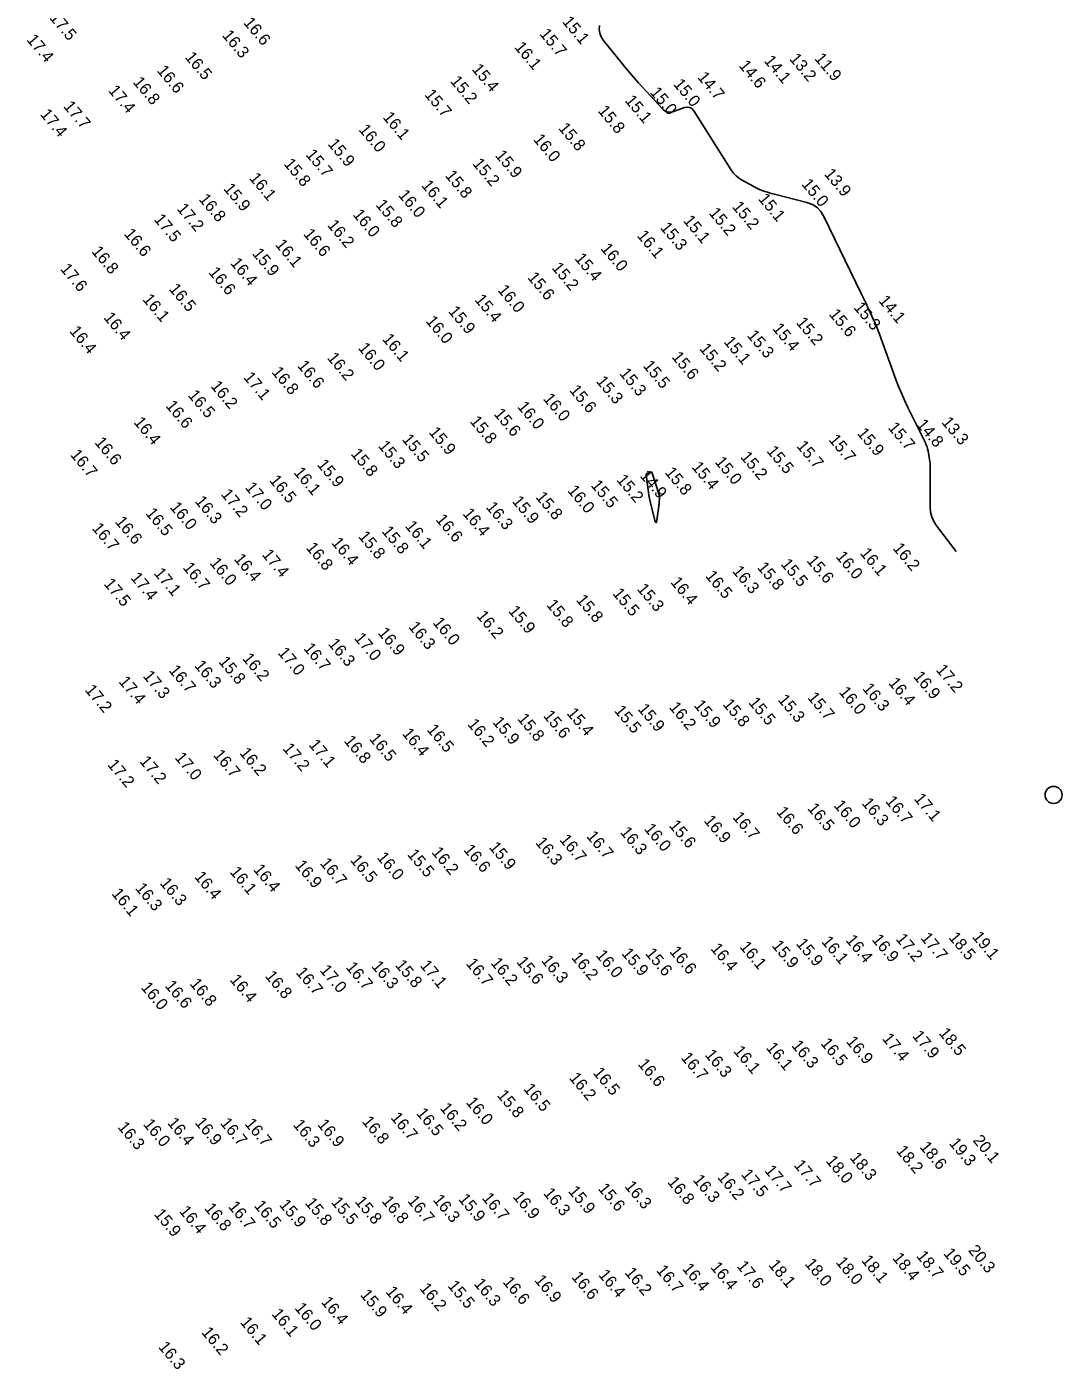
# Model space of a CAD drawing. Extents: x 988130 to 1132882, y 654656 to 841453.
# Drawn here: x 1110747 to 1111185, y 678117 to 678686 of the extents above; entities that cross this region are included whole.
import ezdxf

# ---------------------------------------------------------------- set-up
doc = ezdxf.new("R2010")
doc.units = 0
for name, color, linetype in [('V-CHAN-NAID', 7, 'Continuous'), ('V-TOPO-MAJR', 7, 'Continuous'), ('V-TOPO-SOUN', 7, 'Continuous')]:
    doc.layers.add(name, color=color, linetype=linetype)

msp = doc.modelspace()

# ---------------------------------------------------------------- linework, layer by layer
at = {"layer": 'V-CHAN-NAID'}
msp.add_circle((1111181.63, 678360.27), 3.6, dxfattribs=at)
at = {"layer": 'V-TOPO-MAJR'}
msp.add_lwpolyline([(1110989.43, 678686.06), (1110989.32, 678684.39), (1110989.54, 678682.81), (1110990.11, 678681.31), (1110991.02, 678679.91), (1110998.81, 678670.11), (1111000.48, 678668.04), (1111002.19, 678666), (1111003.95, 678664), (1111005.73, 678662.02), (1111016.24, 678650.64), (1111017.18, 678649.85), (1111018.19, 678649.41), (1111019.3, 678649.32), (1111020.49, 678649.58), (1111025.43, 678651.33), (1111026.6, 678651.57), (1111027.63, 678651.43), (1111028.53, 678650.9), (1111029.3, 678649.99), (1111045.32, 678624.74), (1111046.18, 678623.55), (1111047.18, 678622.49), (1111048.29, 678621.57), (1111049.54, 678620.79), (1111056.3, 678617.11), (1111056.86, 678616.82), (1111057.43, 678616.56), (1111058.01, 678616.32), (1111058.6, 678616.11), (1111061, 678615.31), (1111061.6, 678615.12), (1111062.2, 678614.94), (1111062.81, 678614.77), (1111063.42, 678614.61), (1111077.18, 678611.12), (1111079.5, 678610.28), (1111081.48, 678609.02), (1111083.12, 678607.33), (1111084.41, 678605.22), (1111100.19, 678572.58), (1111100.87, 678571.16), (1111101.55, 678569.74), (1111102.22, 678568.32), (1111102.89, 678566.9), (1111105.54, 678561.2), (1111106.19, 678559.77), (1111106.81, 678558.32), (1111107.39, 678556.86), (1111107.94, 678555.39), (1111114.88, 678536.18), (1111115.99, 678533.24), (1111117.18, 678530.34), (1111118.45, 678527.48), (1111119.8, 678524.64), (1111127.36, 678509.4), (1111127.73, 678508.57), (1111128.05, 678507.72), (1111128.3, 678506.85), (1111128.48, 678505.96), (1111129.11, 678502.37), (1111129.25, 678501.46), (1111129.34, 678500.56), (1111129.4, 678499.65), (1111129.42, 678498.74), (1111129.36, 678482.29), (1111129.53, 678480.08), (1111130.04, 678477.98), (1111130.91, 678476), (1111132.12, 678474.14), (1111140.41, 678463.33)], dxfattribs=at)
msp.add_lwpolyline([(1111009.28, 678496.27), (1111009.19, 678496.03), (1111009.19, 678495.74), (1111010.11, 678488.45), (1111010.3, 678487.13), (1111010.53, 678485.82), (1111010.8, 678484.51), (1111011.12, 678483.22), (1111012.86, 678476.59), (1111013.13, 678475.77), (1111013.36, 678475.51), (1111013.56, 678475.8), (1111013.73, 678476.64), (1111014.5, 678482.59), (1111014.55, 678482.98), (1111014.6, 678483.37), (1111014.64, 678483.77), (1111014.68, 678484.16), (1111014.84, 678485.74), (1111014.85, 678486.14), (1111014.83, 678486.53), (1111014.77, 678486.91), (1111014.68, 678487.29), (1111011.76, 678496.59), (1111011.64, 678496.85), (1111011.46, 678497), (1111011.24, 678497.05), (1111010.96, 678497), (1111009.73, 678496.59), (1111009.46, 678496.46)], close=True, dxfattribs=at)

# ---------------------------------------------------------------- texts
at = {"layer": 'V-TOPO-SOUN'}
for s, p in [('17.5 ', (1110756.35, 678689.25)), ('16.6 ', (1110838.44, 678687.15)), ('15.1 ', (1110973.38, 678687.59)), ('17.4 ', (1110746.68, 678679.96)), ('16.3 ', (1110829.41, 678681.8)), ('15.7 ', (1110963.78, 678682.4)), ('16.1 ', (1110953.15, 678676.81)), ('16.5 ', (1110813.67, 678672.55)), ('14.6 ', (1111048.12, 678669)), ('14.1 ', (1111058.77, 678671.03)), ('13.2 ', (1111069.5, 678671.87)), ('11.9 ', (1111080.15, 678672.01)), ('16.8 ', (1110791.64, 678661.99)), ('16.6 ', (1110801.81, 678666.87)), ('15.2 ', (1110925.97, 678662.39)), ('15.4 ', (1110935.12, 678667.48)), ('14.7 ', (1111030.6, 678664.07)), ('17.4 ', (1110781.26, 678658.42)), ('15.7 ', (1110915.08, 678656.68)), ('15.0 ', (1111010.52, 678657.65)), ('15.0 ', (1111020.4, 678661.14)), ('17.7 ', (1110762.23, 678651.72)), ('15.1 ', (1110999.9, 678654.21)), ('17.4 ', (1110752.39, 678648.36)), ('16.1 ', (1110897.41, 678647.14)), ('15.8 ', (1110988.47, 678649.82)), ('16.0 ', (1110887.24, 678641.88)), ('15.8 ', (1110971.78, 678642.49)), ('15.9 ', (1110874.14, 678635.79)), ('16.0 ', (1110961.11, 678637.76)), ('15.7 ', (1110864.77, 678631.31)), ('15.9 ', (1110944.97, 678630.96)), ('15.8 ', (1110855.5, 678627.38)), ('15.8 ', (1110923.8, 678622.41)), ('15.2 ', (1110935.41, 678627.47)), ('13.9 ', (1111084.22, 678623.12)), ('15.9 ', (1110829.97, 678616.88)), ('16.1 ', (1110840.86, 678621.36)), ('16.1 ', (1110913.77, 678618.26)), ('15.0 ', (1111074.67, 678618.8)), ('16.8 ', (1110819.53, 678612.42)), ('16.0 ', (1110903.94, 678614.16)), ('15.1 ', (1111056.34, 678612.57)), ('17.2 ', (1110810.26, 678608.37)), ('16.0 ', (1110884.73, 678605.92)), ('15.8 ', (1110894.42, 678610.02)), ('15.2 ', (1111035.43, 678606.58)), ('15.2 ', (1111045.3, 678609.22)), ('17.5 ', (1110800.54, 678603.88)), ('16.2 ', (1110873.93, 678601.45)), ('15.3 ', (1111014.82, 678600.37)), ('15.1 ', (1111024.58, 678603.33)), ('16.6 ', (1110787.88, 678597.71)), ('16.6 ', (1110863.78, 678597.69)), ('16.1 ', (1111005.02, 678596.98)), ('16.8 ', (1110774.14, 678590.31)), ('15.9 ', (1110842.15, 678589.41)), ('16.1 ', (1110851.87, 678593.17)), ('16.0 ', (1110989.68, 678591.47)), ('17.6 ', (1110760.9, 678582.89)), ('16.4 ', (1110832.9, 678585.36)), ('15.2 ', (1110968.94, 678583.37)), ('15.4 ', (1110978.64, 678587.31)), ('16.6 ', (1110823.68, 678581.46)), ('15.6 ', (1110958.67, 678579.28)), ('16.5 ', (1110806.91, 678574.41)), ('16.0 ', (1110946.02, 678573.94)), ('16.1 ', (1110795.73, 678570.02)), ('15.4 ', (1110936.3, 678569.86)), ('15.3 ', (1111096.74, 678566.57)), ('14.1 ', (1111107.27, 678569.44)), ('16.4 ', (1110779.24, 678562.3)), ('16.0 ', (1110915.6, 678560.8)), ('15.9 ', (1110925.14, 678564.94)), ('15.2 ', (1111072.36, 678560.16)), ('15.6 ', (1111086.29, 678563.7)), ('16.4 ', (1110764.81, 678556.53)), ('15.3 ', (1111051.59, 678554.73)), ('15.4 ', (1111062.34, 678557.65)), ('16.0 ', (1110886.98, 678549.41)), ('16.1 ', (1110897.19, 678553.21)), ('15.2 ', (1111031.45, 678549.11)), ('15.1 ', (1111041.73, 678552.05)), ('16.2 ', (1110873.87, 678545.24)), ('15.6 ', (1111019.72, 678545.61)), ('17.1 ', (1110838.44, 678536.98)), ('16.8 ', (1110850.39, 678539.23)), ('16.6 ', (1110861.24, 678541.91)), ('15.3 ', (1110997.56, 678538.64)), ('15.5 ', (1111007.55, 678541.87)), ('16.2 ', (1110824.55, 678533.28)), ('15.6 ', (1110976.41, 678531.52)), ('15.3 ', (1110987.72, 678535.32)), ('16.5 ', (1110814.93, 678529.39)), ('16.0 ', (1110965.28, 678527.93)), ('16.6 ', (1110805.49, 678524.95)), ('15.6 ', (1110944.38, 678521.52)), ('16.0 ', (1110954.37, 678524.54)), ('16.4 ', (1110791.99, 678517.97)), ('15.8 ', (1110934.28, 678518.37)), ('15.7 ', (1111111.26, 678515.7)), ('14.8 ', (1111123.36, 678516.99)), ('13.3 ', (1111133.96, 678517.96)), ('16.6 ', (1110775.42, 678509.44)), ('15.5 ', (1110905.57, 678510.71)), ('15.9 ', (1110916.89, 678513.75)), ('15.7 ', (1111086.17, 678510.57)), ('15.9 ', (1111098.18, 678513.29)), ('16.7 ', (1110765.14, 678504.21)), ('15.8 ', (1110883.89, 678504.59)), ('15.3 ', (1110895.47, 678507.93)), ('15.2 ', (1111048.8, 678503.26)), ('15.5 ', (1111059.92, 678505.76)), ('15.7 ', (1111072.54, 678507.91)), ('15.9 ', (1110869.59, 678500.02)), ('15.4 ', (1111028.18, 678499.02)), ('15.0 ', (1111037.97, 678501.15)), ('16.5 ', (1110849.4, 678493.35)), ('16.1 ', (1110859.7, 678496.7)), ('15.2 ', (1110996.35, 678493.58)), ('14.9 ', (1111006.24, 678495.32)), ('15.8 ', (1111016.79, 678496.7)), ('17.2 ', (1110828.95, 678487.45)), ('17.0 ', (1110839.11, 678490.33)), ('15.8 ', (1110962.09, 678486.27)), ('16.0 ', (1110975.61, 678489.04)), ('15.5 ', (1110985.49, 678491.26)), ('16.0 ', (1110807.3, 678482)), ('16.3 ', (1110817.88, 678484.52)), ('16.3 ', (1110941.06, 678482.03)), ('15.9 ', (1110952.13, 678484.53)), ('16.6 ', (1110784.11, 678475.85)), ('16.5 ', (1110797, 678479.43)), ('16.6 ', (1110919.81, 678476.77)), ('16.4 ', (1110931.24, 678479.29)), ('16.7 ', (1110774.32, 678473.1)), ('15.8 ', (1110887.05, 678469.62)), ('15.8 ', (1110896.98, 678471.78)), ('16.1 ', (1110906.87, 678474)), ('16.8 ', (1110864.91, 678464.84)), ('16.4 ', (1110875.69, 678466.94)), ('16.2 ', (1111113.3, 678464.61)), ('16.0 ', (1110824.14, 678458.4)), ('16.4 ', (1110834.46, 678460.06)), ('17.4 ', (1110846.28, 678461.93)), ('15.5 ', (1111065.88, 678457.93)), ('15.6 ', (1111076.87, 678459.34)), ('16.0 ', (1111089.15, 678461.07)), ('16.1 ', (1111099.42, 678462.54)), ('17.4 ', (1110790.64, 678452.13)), ('17.1 ', (1110800.53, 678454.05)), ('16.7 ', (1110812.78, 678456.41)), ('16.5 ', (1111033.96, 678452.89)), ('16.3 ', (1111045.34, 678454.95)), ('15.8 ', (1111055.89, 678456.49)), ('17.5 ', (1110779.32, 678449.56)), ('15.3 ', (1111005.02, 678447.39)), ('16.4 ', (1111019.23, 678450.23)), ('15.8 ', (1110966.67, 678440.66)), ('15.8 ', (1110979.26, 678442.74)), ('15.5 ', (1110994.67, 678445.46)), ('16.2 ', (1110937.09, 678435.94)), ('15.9 ', (1110950.57, 678438.06)), ('16.3 ', (1110908.29, 678431.33)), ('16.0 ', (1110918.6, 678433.13)), ('16.3 ', (1110874.27, 678424.16)), ('17.0 ', (1110885.32, 678426.55)), ('16.9 ', (1110895.36, 678428.76)), ('16.2 ', (1110837.96, 678417.94)), ('17.0 ', (1110852.99, 678420.36)), ('16.7 ', (1110863.84, 678422.25)), ('16.7 ', (1110806.83, 678412.92)), ('16.3 ', (1110817.66, 678414.92)), ('15.8 ', (1110827.89, 678416.58)), ('17.2 ', (1111131.56, 678413.15)), ('17.4 ', (1110785.62, 678408.17)), ('17.3 ', (1110795.89, 678410.52)), ('16.4 ', (1111111.45, 678407.59)), ('16.9 ', (1111121.98, 678410.26)), ('17.2 ', (1110771.36, 678404.59)), ('15.3 ', (1111064.65, 678400.45)), ('15.7 ', (1111077.16, 678401.42)), ('16.0 ', (1111090.49, 678403.74)), ('16.3 ', (1111100.46, 678405.21)), ('15.4 ', (1110975.27, 678394.73)), ('15.5 ', (1110995.37, 678395.84)), ('15.9 ', (1111005.36, 678396.54)), ('16.2 ', (1111018.6, 678397.28)), ('15.9 ', (1111029.08, 678398.12)), ('15.8 ', (1111041.31, 678398.57)), ('15.5 ', (1111052.24, 678399.27)), ('16.2 ', (1110933.27, 678390.13)), ('15.9 ', (1110943.87, 678391.02)), ('15.8 ', (1110954.4, 678392.41)), ('15.6 ', (1110965.32, 678393.7)), ('16.5 ', (1110891.66, 678383.96)), ('16.4 ', (1110905.57, 678386.15)), ('16.5 ', (1110916.06, 678387.8)), ('16.2 ', (1110836.76, 678377.94)), ('17.2 ', (1110855.04, 678379.83)), ('17.1 ', (1110866.08, 678381.42)), ('16.8 ', (1110880.99, 678383.06)), ('17.2 ', (1110780.87, 678372.96)), ('17.2 ', (1110794.43, 678374.42)), ('17.0 ', (1110809.37, 678375.95)), ('16.7 ', (1110825.65, 678377.07)), ('16.0 ', (1111088.32, 678355.71)), ('16.3 ', (1111100.15, 678356.67)), ('16.7 ', (1111110.16, 678357.5)), ('17.1 ', (1111122.26, 678358.56)), ('16.9 ', (1111033.34, 678349.28)), ('16.7 ', (1111045.47, 678350.76)), ('16.6 ', (1111064.02, 678352.95)), ('16.5 ', (1111077.17, 678354.46)), ('16.3 ', (1110997.87, 678344.4)), ('16.0 ', (1111008.04, 678345.8)), ('15.6 ', (1111018.55, 678347.24)), ('15.9 ', (1110942.37, 678338.02)), ('16.3 ', (1110962.01, 678340)), ('16.7 ', (1110972.23, 678341.18)), ('16.7 ', (1110983.6, 678342.65)), ('16.5 ', (1110883.64, 678332.57)), ('16.0 ', (1110894.91, 678333.69)), ('15.5 ', (1110907.79, 678334.95)), ('16.2 ', (1110918.09, 678335.89)), ('16.6 ', (1110931.58, 678336.94)), ('16.1 ', (1110832.64, 678327.57)), ('16.4 ', (1110842.59, 678328.61)), ('16.9 ', (1110860.25, 678330.29)), ('16.7 ', (1110870.82, 678331.24)), ('16.3 ', (1110803.06, 678322.83)), ('16.4 ', (1110817.64, 678325.51)), ('16.1 ', (1110782.65, 678318.37)), ('16.3 ', (1110792.63, 678320.66)), ('16.1 ', (1111083.08, 678298.1)), ('16.4 ', (1111093.36, 678298.68)), ('16.9 ', (1111104.44, 678298.91)), ('17.2 ', (1111114.55, 678299.18)), ('17.7 ', (1111125.06, 678299.6)), ('18.5 ', (1111136.93, 678299.78)), ('19.1 ', (1111146.93, 678300.06)), ('15.9 ', (1110998.49, 678293.05)), ('15.6 ', (1111008.5, 678293.04)), ('16.6 ', (1111018.79, 678293.85)), ('16.4 ', (1111036.19, 678295.1)), ('16.1 ', (1111048.45, 678295.89)), ('15.9 ', (1111062.08, 678296.36)), ('15.9 ', (1111072.35, 678297.18)), ('16.7 ', (1110881.75, 678287.19)), ('16.3 ', (1110892.65, 678287.63)), ('15.8 ', (1110902.66, 678288.1)), ('17.1 ', (1110913.17, 678287.95)), ('16.7 ', (1110932.63, 678288.77)), ('16.2 ', (1110943.11, 678289.01)), ('15.6 ', (1110954.03, 678289.49)), ('16.3 ', (1110964.49, 678290.05)), ('16.2 ', (1110977.22, 678291.34)), ('16.0 ', (1110987.55, 678292.28)), ('16.4 ', (1110832.66, 678281.89)), ('16.8 ', (1110847.58, 678283.45)), ('16.7 ', (1110860.64, 678284.98)), ('17.0 ', (1110870.73, 678285.96)), ('16.0 ', (1110795.04, 678278.66)), ('16.6 ', (1110805.18, 678279.36)), ('16.8 ', (1110815.71, 678280.22)), ('18.5 ', (1111132.76, 678259.31)), ('16.1 ', (1111059.63, 678253.13)), ('16.3 ', (1111070.43, 678254.05)), ('16.5 ', (1111082.72, 678254.96)), ('16.9 ', (1111093.55, 678255.75)), ('17.4 ', (1111108.79, 678256.98)), ('17.9 ', (1111121.56, 678258.12)), ('16.7 ', (1111023.66, 678248.89)), ('16.3 ', (1111033.72, 678250.13)), ('16.1 ', (1111045.85, 678251.68)), ('16.5 ', (1110986.36, 678242.54)), ('16.6 ', (1111005.38, 678246.18)), ('16.5 ', (1110956.95, 678235.7)), ('16.2 ', (1110976.3, 678240.36)), ('16.0 ', (1110932.64, 678229.98)), ('15.8 ', (1110945.76, 678233.02)), ('16.5 ', (1110911.59, 678225.35)), ('16.2 ', (1110921.62, 678227.54)), ('16.3 ', (1110785.23, 678219.51)), ('16.0 ', (1110796, 678220.73)), ('16.4 ', (1110806.23, 678221.27)), ('16.9 ', (1110817.88, 678221.4)), ('16.7 ', (1110828.6, 678221.17)), ('16.7 ', (1110838.96, 678220.91)), ('16.3 ', (1110859.45, 678220.49)), ('16.9 ', (1110869.73, 678220.59)), ('16.8 ', (1110888.66, 678221.89)), ('16.7 ', (1110900.75, 678223.52)), ('20.1 ', (1111147.2, 678213.88)), ('18.2 ', (1111114.74, 678209.47)), ('18.6 ', (1111124.7, 678211.1)), ('19.3 ', (1111137.12, 678212.64)), ('17.7 ', (1111071.42, 678203.39)), ('18.0 ', (1111084.96, 678205.2)), ('18.3 ', (1111095.08, 678206.53)), ('16.8 ', (1111017.91, 678196.25)), ('16.3 ', (1111028.68, 678197.12)), ('16.2 ', (1111039.05, 678198.27)), ('17.5 ', (1111049.11, 678199.45)), ('17.7 ', (1111058.99, 678201.12)), ('16.3 ', (1110965.37, 678191.52)), ('15.9 ', (1110975.92, 678192.35)), ('15.6 ', (1110988.52, 678193.46)), ('16.3 ', (1110999.77, 678194.44)), ('16.8 ', (1110821.89, 678185.11)), ('16.7 ', (1110831.97, 678185.87)), ('16.5 ', (1110842.96, 678186.23)), ('15.9 ', (1110853.56, 678186.62)), ('15.8 ', (1110864.54, 678187.34)), ('15.5 ', (1110875.55, 678187.72)), ('15.8 ', (1110885.61, 678187.97)), ('16.8 ', (1110896.96, 678188.16)), ('16.7 ', (1110907.86, 678188.26)), ('16.3 ', (1110918.63, 678188.71)), ('15.9 ', (1110929.4, 678189.01)), ('16.7 ', (1110939.45, 678189.46)), ('16.9 ', (1110952.43, 678190.08)), ('15.9 ', (1110800.6, 678182.65)), ('16.4 ', (1110811.23, 678183.92)), ('20.3 ', (1111145.23, 678167.31)), ('18.0 ', (1111089.17, 678162.3)), ('18.1 ', (1111099.97, 678163.06)), ('18.4 ', (1111113.13, 678164.06)), ('18.7 ', (1111123.27, 678164.9)), ('19.5 ', (1111134.74, 678166.02)), ('16.6 ', (1110977.3, 678156.04)), ('16.4 ', (1110988.7, 678156.94)), ('16.2 ', (1110999.84, 678157.86)), ('16.7 ', (1111013.17, 678158.85)), ('16.4 ', (1111024.16, 678159.55)), ('16.4 ', (1111036.13, 678160.17)), ('17.6 ', (1111047.26, 678160.66)), ('18.1 ', (1111060.71, 678161.13)), ('18.0 ', (1111076.05, 678161.63)), ('16.2 ', (1110912.99, 678151.24)), ('15.5 ', (1110924.89, 678152.31)), ('16.3 ', (1110935.96, 678153.19)), ('16.6 ', (1110948.18, 678153.93)), ('16.9 ', (1110961.62, 678154.68)), ('16.4 ', (1110871.32, 678145.48)), ('15.9 ', (1110887.85, 678148.51)), ('16.4 ', (1110898.62, 678149.82)), ('16.1 ', (1110850.37, 678140.39)), ('16.0 ', (1110860.1, 678142.9)), ('16.1 ', (1110837.04, 678136.88)), ('16.2 ', (1110820.67, 678132.62)), ('16.3 ', (1110802.42, 678126.44))]:
    msp.add_text(s, height=5, rotation=310, dxfattribs=at).set_placement(p)

doc.saveas('drawing.dxf')
